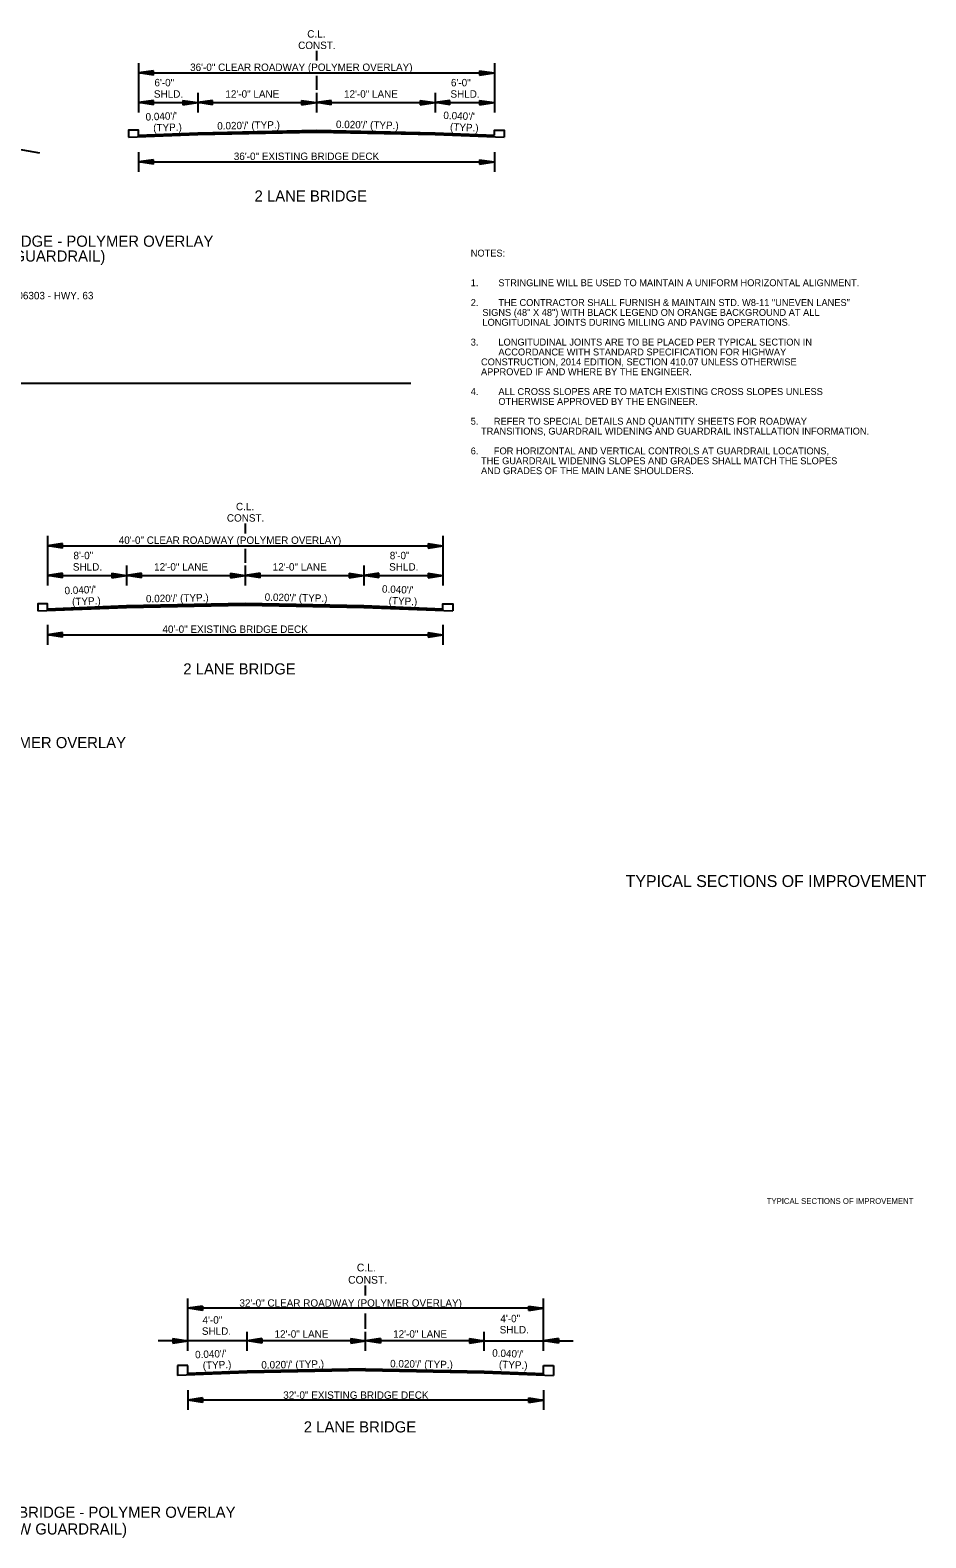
# Model space of a CAD drawing. Extents: x 545241 to 1930787, y -1971772 to 596640.
# Drawn here: x 547362 to 548268, y -1967230 to -1965705 of the extents above; entities that cross this region are included whole.
import ezdxf

# ---------------------------------------------------------------- set-up
doc = ezdxf.new("R2010")
doc.units = 0
for name, color, linetype in [('R_Border', 7, 'Continuous'), ('R_Border Notes', 7, 'Continuous'), ('R_Border Prem', 7, 'Continuous'), ('R_Draft', 7, 'Continuous')]:
    doc.layers.add(name, color=color, linetype=linetype)

# ---------------------------------------------------------------- blocks, each defined once
blk = doc.blocks.new('ARROW')
at = {"layer": 'R_Draft'}
for p, q in [((-2, 0.3), (0, 0)), ((-2, 0.3), (-2, -0.3)), ((-2, 0.25), (-0.334, 0)), ((-2, 0.199), (-0.678, 0)), ((-2, 0.149), (-1.011, 0)), ((-2, 0.097), (-1.35, 0)), ((-2, 0.047), (-1.684, 0)), ((-2, -0.3), (0, 0)), ((-2, -0.098), (-1.35, 0)), ((-2, -0.199), (-0.678, 0)), ((-2, -0.25), (-0.334, 0)), ((-2, -0.149), (-1.011, 0)), ((-2, -0.047), (-1.684, 0))]:
    blk.add_line(p, q, dxfattribs=at)

msp = doc.modelspace()

# ---------------------------------------------------------------- linework, layer by layer
at = {"layer": 'R_Border'}
for p, q in [((547651.3, -1965726.1), (547651.3, -1965736.1)), ((547471.3, -1965738.6), (547471.3, -1965788.6)), ((547471.3, -1965748.6), (547831.3, -1965748.6)), ((547831.3, -1965738.6), (547831.3, -1965788.6)), ((547651.3, -1965751.6), (547651.3, -1965765.6)), ((547471.3, -1965778.6), (547831.3, -1965778.6)), ((547531.3, -1965768.6), (547531.3, -1965788.6)), ((547651.3, -1965768.6), (547651.3, -1965788.6)), ((547771.3, -1965768.6), (547771.3, -1965788.6)), ((547271.3, -1965811.4), (547371.3, -1965829.4)), ((547471.3, -1965828.6), (547471.3, -1965848.6)), ((547471.3, -1965838.6), (547831.3, -1965838.6)), ((547831.3, -1965828.6), (547831.3, -1965848.6)), ((546718.9, -1966062.1), (547746.9, -1966062.1)), ((547579.3, -1966204.2), (547579.3, -1966214.2)), ((547379.3, -1966216.7), (547379.3, -1966266.7)), ((547779.3, -1966216.7), (547779.3, -1966266.7)), ((547379.3, -1966226.7), (547779.3, -1966226.7)), ((547579.3, -1966229.7), (547579.3, -1966243.7)), ((547459.3, -1966246.7), (547459.3, -1966266.7)), ((547579.3, -1966246.7), (547579.3, -1966266.7)), ((547699.3, -1966246.7), (547699.3, -1966266.7)), ((547379.3, -1966256.7), (547779.3, -1966256.7)), ((547379.3, -1966306.7), (547379.3, -1966326.7)), ((547779.3, -1966306.7), (547779.3, -1966326.7)), ((547379.3, -1966316.7), (547779.3, -1966316.7)), ((547521.1, -1967030.4), (547491.1, -1967030.4)), ((547881.1, -1967030.4), (547911.1, -1967030.4)), ((547521.1, -1967055.3), (547510.9, -1967055.3)), ((547510.9, -1967055.3), (547510.9, -1967065.4)), ((547521.1, -1967064.7), (547521.1, -1967055.3)), ((547881.1, -1967064.7), (547881.1, -1967055.3)), ((547881.1, -1967055.3), (547891.3, -1967055.3)), ((547891.3, -1967055.3), (547891.3, -1967065.4))]:
    msp.add_line(p, q, dxfattribs=at)
for points in [[(547471.3, -1965812.9), (547471.3, -1965806.4), (547461.3, -1965806.4), (547461.3, -1965813.6)], [(547461.3, -1965813.6), (547531.3, -1965810.8), (547651.3, -1965808.4), (547771.3, -1965810.8), (547841.3, -1965813.6)], [(547471.3, -1965811.4), (547531.3, -1965809), (547651.3, -1965806.6), (547771.3, -1965809), (547831.3, -1965811.4)], [(547471.3, -1965811.7), (547531.3, -1965809.3), (547651.3, -1965806.9), (547771.3, -1965809.3), (547831.3, -1965811.7)], [(547471.3, -1965812), (547531.3, -1965809.6), (547651.3, -1965807.2), (547771.3, -1965809.6), (547831.3, -1965812)], [(547471.3, -1965812.3), (547531.3, -1965809.9), (547651.3, -1965807.5), (547771.3, -1965809.9), (547831.3, -1965812.3)], [(547471.3, -1965812.6), (547531.3, -1965810.2), (547651.3, -1965807.8), (547771.3, -1965810.2), (547831.3, -1965812.6)], [(547471.3, -1965812.9), (547531.3, -1965810.5), (547651.3, -1965808.1), (547771.3, -1965810.5), (547831.3, -1965812.9)], [(547831.3, -1965811.4), (547831.3, -1965806.4), (547841.3, -1965806.4), (547841.3, -1965813.6)], [(547379.3, -1966291.8), (547379.3, -1966285.3), (547369.3, -1966285.3), (547369.3, -1966292.5)], [(547369.3, -1966292.5), (547459.3, -1966288.9), (547579.3, -1966286.5), (547699.3, -1966288.9), (547789.3, -1966292.5)], [(547379.3, -1966290.3), (547459.3, -1966287.1), (547579.3, -1966284.7), (547699.3, -1966287.1), (547779.3, -1966290.3)], [(547379.3, -1966290.6), (547459.3, -1966287.4), (547579.3, -1966285), (547699.3, -1966287.4), (547779.3, -1966290.6)], [(547379.3, -1966290.9), (547459.3, -1966287.7), (547579.3, -1966285.3), (547699.3, -1966287.7), (547779.3, -1966290.9)], [(547379.3, -1966291.2), (547459.3, -1966288), (547579.3, -1966285.6), (547699.3, -1966288), (547779.3, -1966291.2)], [(547379.3, -1966291.5), (547459.3, -1966288.3), (547579.3, -1966285.9), (547699.3, -1966288.3), (547779.3, -1966291.5)], [(547379.3, -1966291.8), (547459.3, -1966288.6), (547579.3, -1966286.2), (547699.3, -1966288.6), (547779.3, -1966291.8)], [(547779.3, -1966292.5), (547779.3, -1966285.3), (547789.3, -1966285.3), (547789.3, -1966292.5)]]:
    msp.add_lwpolyline(points, dxfattribs=at)
at = {"layer": 'R_Draft'}
for p, q in [((547701.1, -1966984.5), (547701.1, -1966974.5)), ((547521.1, -1967040.4), (547521.1, -1966987.5)), ((547536.1, -1966995.3), (547521.1, -1966997.5)), ((547881.1, -1966997.5), (547521.1, -1966997.5)), ((547536.1, -1966999.8), (547521.1, -1966997.5)), ((547536.1, -1966995.7), (547523.6, -1966997.5)), ((547536.1, -1966999.4), (547523.6, -1966997.5)), ((547536.1, -1966996), (547526.2, -1966997.5)), ((547536.1, -1966999), (547526.2, -1966997.5)), ((547536.1, -1966996.4), (547528.7, -1966997.5)), ((547536.1, -1966998.7), (547528.7, -1966997.5)), ((547536.1, -1966996.8), (547531.2, -1966997.5)), ((547536.1, -1966998.3), (547531.2, -1966997.5)), ((547536.1, -1966997.2), (547533.7, -1966997.5)), ((547536.1, -1966997.9), (547533.7, -1966997.5)), ((547536.1, -1966995.3), (547536.1, -1966999.8)), ((547871.1, -1966997.5), (547591.1, -1966997.5)), ((547866.1, -1966995.3), (547881.1, -1966997.5)), ((547866.1, -1966999.8), (547866.1, -1966995.3)), ((547866.1, -1966995.7), (547878.6, -1966997.5)), ((547866.1, -1966996), (547876, -1966997.5)), ((547866.1, -1966996.4), (547873.5, -1966997.5)), ((547866.1, -1966996.8), (547871, -1966997.5)), ((547866.1, -1966997.2), (547868.5, -1966997.5)), ((547866.1, -1966999.8), (547881.1, -1966997.5)), ((547866.1, -1966998.3), (547871, -1966997.5)), ((547866.1, -1966999), (547876, -1966997.5)), ((547866.1, -1966999.4), (547878.6, -1966997.5)), ((547866.1, -1966998.7), (547873.5, -1966997.5)), ((547866.1, -1966997.9), (547868.5, -1966997.5)), ((547881.1, -1967040.4), (547881.1, -1966987.6)), ((547701.1, -1967018.3), (547701.1, -1967002.6)), ((547506.1, -1967028.1), (547521.1, -1967030.4)), ((547506.1, -1967028.1), (547506.1, -1967032.6)), ((547506.1, -1967028.5), (547518.6, -1967030.4)), ((547506.1, -1967028.9), (547516, -1967030.4)), ((547506.1, -1967029.2), (547513.5, -1967030.4)), ((547506.1, -1967029.6), (547511, -1967030.4)), ((547581.1, -1967040.4), (547581.1, -1967021.2)), ((547596.1, -1967028.1), (547581.1, -1967030.4)), ((547596.1, -1967028.5), (547583.6, -1967030.4)), ((547596.1, -1967028.9), (547586.2, -1967030.4)), ((547596.1, -1967029.2), (547588.7, -1967030.4)), ((547596.1, -1967029.6), (547591.2, -1967030.4)), ((547596.1, -1967028.1), (547596.1, -1967032.6)), ((547686.1, -1967028.1), (547701.1, -1967030.4)), ((547686.1, -1967028.1), (547686.1, -1967032.6)), ((547686.1, -1967028.5), (547698.6, -1967030.4)), ((547686.1, -1967028.9), (547696, -1967030.4)), ((547686.1, -1967029.2), (547693.5, -1967030.4)), ((547686.1, -1967029.6), (547691, -1967030.4)), ((547701.1, -1967040.4), (547701.1, -1967021.2)), ((547716.1, -1967028.1), (547701.1, -1967030.4)), ((547716.1, -1967028.5), (547703.6, -1967030.4)), ((547716.1, -1967028.9), (547706.2, -1967030.4)), ((547716.1, -1967029.2), (547708.7, -1967030.4)), ((547716.1, -1967029.6), (547711.2, -1967030.4)), ((547716.1, -1967028.1), (547716.1, -1967032.6)), ((547806.1, -1967028.1), (547821.1, -1967030.4)), ((547806.1, -1967028.1), (547806.1, -1967032.6)), ((547806.1, -1967028.5), (547818.6, -1967030.4)), ((547806.1, -1967028.9), (547816, -1967030.4)), ((547806.1, -1967029.2), (547813.5, -1967030.4)), ((547806.1, -1967029.6), (547811, -1967030.4)), ((547821.1, -1967040.4), (547821.1, -1967021.2)), ((547896.1, -1967028.1), (547881.1, -1967030.4)), ((547896.1, -1967028.5), (547883.6, -1967030.4)), ((547896.1, -1967028.9), (547886.2, -1967030.4)), ((547896.1, -1967029.2), (547888.7, -1967030.4)), ((547896.1, -1967029.6), (547891.2, -1967030.4)), ((547896.1, -1967028.1), (547896.1, -1967032.6)), ((547506.1, -1967030), (547508.5, -1967030.4)), ((547506.1, -1967032.6), (547521.1, -1967030.4)), ((547506.1, -1967031.1), (547511, -1967030.4)), ((547506.1, -1967031.9), (547516, -1967030.4)), ((547506.1, -1967032.2), (547518.6, -1967030.4)), ((547506.1, -1967031.5), (547513.5, -1967030.4)), ((547506.1, -1967030.7), (547508.5, -1967030.4)), ((547581.1, -1967030.4), (547521.1, -1967030.4)), ((547701.1, -1967030.4), (547581.1, -1967030.4)), ((547596.1, -1967032.6), (547581.1, -1967030.4)), ((547596.1, -1967032.2), (547583.6, -1967030.4)), ((547596.1, -1967031.9), (547586.2, -1967030.4)), ((547596.1, -1967031.5), (547588.7, -1967030.4)), ((547596.1, -1967031.1), (547591.2, -1967030.4)), ((547596.1, -1967030), (547593.7, -1967030.4)), ((547596.1, -1967030.7), (547593.7, -1967030.4)), ((547686.1, -1967030), (547688.5, -1967030.4)), ((547686.1, -1967032.6), (547701.1, -1967030.4)), ((547686.1, -1967031.1), (547691, -1967030.4)), ((547686.1, -1967031.9), (547696, -1967030.4)), ((547686.1, -1967032.2), (547698.6, -1967030.4)), ((547686.1, -1967031.5), (547693.5, -1967030.4)), ((547686.1, -1967030.7), (547688.5, -1967030.4)), ((547821.1, -1967030.4), (547701.1, -1967030.4)), ((547716.1, -1967032.6), (547701.1, -1967030.4)), ((547716.1, -1967032.2), (547703.6, -1967030.4)), ((547716.1, -1967031.9), (547706.2, -1967030.4)), ((547716.1, -1967031.5), (547708.7, -1967030.4)), ((547716.1, -1967031.1), (547711.2, -1967030.4)), ((547716.1, -1967030), (547713.7, -1967030.4)), ((547716.1, -1967030.7), (547713.7, -1967030.4)), ((547806.1, -1967030), (547808.5, -1967030.4)), ((547806.1, -1967032.6), (547821.1, -1967030.4)), ((547806.1, -1967031.1), (547811, -1967030.4)), ((547806.1, -1967031.9), (547816, -1967030.4)), ((547806.1, -1967032.2), (547818.6, -1967030.4)), ((547806.1, -1967031.5), (547813.5, -1967030.4)), ((547806.1, -1967030.7), (547808.5, -1967030.4)), ((547821.1, -1967030.4), (547881.1, -1967030.4)), ((547896.1, -1967032.6), (547881.1, -1967030.4)), ((547896.1, -1967032.2), (547883.6, -1967030.4)), ((547896.1, -1967031.9), (547886.2, -1967030.4)), ((547896.1, -1967031.5), (547888.7, -1967030.4)), ((547896.1, -1967031.1), (547891.2, -1967030.4)), ((547896.1, -1967030), (547893.7, -1967030.4)), ((547896.1, -1967030.7), (547893.7, -1967030.4)), ((547701.1, -1967058.7), (547581.1, -1967061.1)), ((547701.1, -1967059), (547581.1, -1967061.4)), ((547701.1, -1967059.3), (547581.1, -1967061.7)), ((547701.1, -1967059.6), (547581.1, -1967062)), ((547701.1, -1967059.9), (547581.1, -1967062.3)), ((547701.1, -1967058.7), (547821.1, -1967061.1)), ((547701.1, -1967059), (547821.1, -1967061.4)), ((547701.1, -1967059.3), (547821.1, -1967061.7)), ((547701.1, -1967059.6), (547821.1, -1967062)), ((547701.1, -1967059.9), (547821.1, -1967062.3)), ((547581.1, -1967062.6), (547510.9, -1967065.4)), ((547581.1, -1967061.1), (547521.1, -1967063.5)), ((547581.1, -1967061.4), (547521.1, -1967063.8)), ((547581.1, -1967061.7), (547521.1, -1967064.1)), ((547581.1, -1967062), (547521.1, -1967064.4)), ((547581.1, -1967062.3), (547521.1, -1967064.7)), ((547701.1, -1967060.2), (547581.1, -1967062.6)), ((547701.1, -1967060.3), (547581.1, -1967062.7)), ((547701.1, -1967060.2), (547821.1, -1967062.6)), ((547701.1, -1967060.3), (547821.1, -1967062.7)), ((547821.1, -1967061.1), (547881.1, -1967063.5)), ((547821.1, -1967061.4), (547881.1, -1967063.8)), ((547821.1, -1967061.7), (547881.1, -1967064.1)), ((547821.1, -1967062), (547881.1, -1967064.4)), ((547821.1, -1967062.3), (547881.1, -1967064.7)), ((547821.1, -1967062.6), (547891.3, -1967065.4)), ((547521.1, -1967080.3), (547521.1, -1967100.3)), ((547536.1, -1967088.1), (547521.1, -1967090.3)), ((547536.1, -1967092.6), (547521.1, -1967090.3)), ((547881.1, -1967090.3), (547521.1, -1967090.3)), ((547536.1, -1967088.5), (547523.6, -1967090.3)), ((547536.1, -1967092.2), (547523.6, -1967090.3)), ((547536.1, -1967088.8), (547526.2, -1967090.3)), ((547536.1, -1967091.8), (547526.2, -1967090.3)), ((547536.1, -1967089.2), (547528.7, -1967090.3)), ((547536.1, -1967091.5), (547528.7, -1967090.3)), ((547536.1, -1967089.6), (547531.2, -1967090.3)), ((547536.1, -1967091.1), (547531.2, -1967090.3)), ((547536.1, -1967090), (547533.7, -1967090.3)), ((547536.1, -1967090.7), (547533.7, -1967090.3)), ((547536.1, -1967088.1), (547536.1, -1967092.6)), ((547866.1, -1967088.1), (547881.1, -1967090.3)), ((547866.1, -1967092.6), (547866.1, -1967088.1)), ((547866.1, -1967088.5), (547878.6, -1967090.3)), ((547866.1, -1967088.8), (547876, -1967090.3)), ((547866.1, -1967089.2), (547873.5, -1967090.3)), ((547866.1, -1967089.6), (547871, -1967090.3)), ((547866.1, -1967090), (547868.5, -1967090.3)), ((547866.1, -1967092.6), (547881.1, -1967090.3)), ((547866.1, -1967091.1), (547871, -1967090.3)), ((547866.1, -1967091.8), (547876, -1967090.3)), ((547866.1, -1967092.2), (547878.6, -1967090.3)), ((547866.1, -1967091.5), (547873.5, -1967090.3)), ((547866.1, -1967090.7), (547868.5, -1967090.3)), ((547881.1, -1967080.1), (547881.1, -1967100.1))]:
    msp.add_line(p, q, dxfattribs=at)

# ---------------------------------------------------------------- block references
at = {"layer": 'R_Border', "xscale": 7.5, "yscale": 7.5, "rotation": 180}
for p in [(547471.3, -1965748.6), (547471.3, -1965778.6), (547531.3, -1965778.6), (547651.3, -1965778.6), (547771.3, -1965778.6), (547471.3, -1965838.6), (547379.3, -1966226.7), (547379.3, -1966256.7), (547459.3, -1966256.7), (547579.3, -1966256.7), (547699.3, -1966256.7), (547379.3, -1966316.7)]:
    msp.add_blockref('ARROW', p, dxfattribs=at)
at = {"layer": 'R_Border', "xscale": 7.5, "yscale": 7.5}
for p in [(547831.3, -1965748.6), (547531.3, -1965778.6), (547651.3, -1965778.6), (547771.3, -1965778.6), (547831.3, -1965778.6), (547831.3, -1965838.6), (547779.3, -1966226.7), (547459.3, -1966256.7), (547579.3, -1966256.7), (547699.3, -1966256.7), (547779.3, -1966256.7), (547779.3, -1966316.7)]:
    msp.add_blockref('ARROW', p, dxfattribs=at)

# ---------------------------------------------------------------- texts
at = {"layer": 'R_Border'}
for s, height, p in [('CONST.', 7.5, (547632.8, -1965724.4)), ('C.L.', 7.5, (547642, -1965712.9)), ('36\'-0" CLEAR ROADWAY (POLYMER OVERLAY)', 7.5, (547523.5, -1965746.6)), ('6\'-0"', 7.5, (547487.4, -1965762.1)), ('6\'-0"', 7.5, (547787.4, -1965762.1)), ('SHLD.', 7.5, (547486.9, -1965773.6)), ('12\'-0" LANE', 7.5, (547559.2, -1965773.6)), ('12\'-0" LANE', 7.5, (547679.2, -1965773.6)), ('SHLD.', 7.5, (547786.9, -1965773.6)), ('36\'-0" EXISTING BRIDGE DECK', 7.5, (547567.7, -1965836.6)), ('2 LANE BRIDGE', 11.25, (547588.7, -1965878.6)), ('36 FT. CLEAR ROADWAY BRIDGE - POLYMER OVERLAY', 11.25, (547143.3, -1965924.3)), ('(NEW GUARDRAIL)', 11.25, (547300.7, -1965939.3)), ('- BR NO. 06303 - HWY. 63', 7.5, (547305.3, -1965977.4)), ('C.L.', 7.5, (547569.9, -1966190.7)), ('CONST.', 7.5, (547560.7, -1966202.2)), ('40\'-0" CLEAR ROADWAY (POLYMER OVERLAY)', 7.5, (547451.3, -1966224.7)), ('8\'-0"', 7.5, (547405.5, -1966240.2)), ('8\'-0"', 7.5, (547725.5, -1966240.2)), ('SHLD.', 7.5, (547404.9, -1966251.7)), ('12\'-0" LANE', 7.5, (547487.1, -1966251.7)), ('12\'-0" LANE', 7.5, (547607.1, -1966251.7)), ('SHLD.', 7.5, (547724.9, -1966251.7)), ('40\'-0" EXISTING BRIDGE DECK', 7.5, (547495.5, -1966314.7)), ('2 LANE BRIDGE', 11.25, (547516.6, -1966356.7)), ('40 FT. CLEAR ROADWAY BRIDGE - POLYMER OVERLAY', 11.25, (547054.9, -1966431.2))]:
    msp.add_text(s, height=height, dxfattribs=at).set_placement(p)
for s, height, rotation, p in [("0.040'/'", 7.5, 2.2916, (547478.6, -1965796.8)), ("0.040'/'", 7.5, 357.7084, (547779.6, -1965795.1)), ('(TYP.)', 7.5, 2.2916, (547486.3, -1965808)), ("0.020'/' (TYP.)", 7.5, 1.1458, (547551, -1965805.9)), ("0.020'/' (TYP.)", 7.5, 358.8542, (547671, -1965804.2)), ('(TYP.)', 7.5, 357.7084, (547786.3, -1965806.8)), ("0.040'/' ", 7.5, 2.2916, (547396.6, -1966275.7)), ("0.040'/'", 7.5, 357.7084, (547717.5, -1966273.9)), ('(TYP.)', 7.5, 2.2916, (547404.2, -1966286.9)), ("0.020'/' (TYP.)", 7.5, 1.1458, (547478.9, -1966283.9)), ("0.020'/' (TYP.)", 7.5, 358.8542, (547598.9, -1966282.2)), ('(TYP.)', 7.5, 357.7084, (547724.2, -1966285.7)), ('TYPICAL SECTIONS OF IMPROVEMENT', 12, 360, (547964.2, -1966571.6))]:
    msp.add_text(s, height=height, rotation=rotation, dxfattribs=at).set_placement(p)
at = {"layer": 'R_Border Notes'}
for s, p in [('NOTES: ', (547807.4, -1965934.2)), ('1.', (547807.4, -1965964.2)), ('STRINGLINE WILL BE USED TO MAINTAIN A UNIFORM HORIZONTAL ALIGNMENT.', (547835.4, -1965964.2)), ('2.', (547807.4, -1965984.2)), ('THE CONTRACTOR SHALL FURNISH & MAINTAIN STD. W8-11 "UNEVEN LANES" ', (547835.4, -1965984.2)), ('    SIGNS (48" X 48") WITH BLACK LEGEND ON ORANGE BACKGROUND AT ALL ', (547808.8, -1965994.2)), ('    LONGITUDINAL JOINTS DURING MILLING AND PAVING OPERATIONS.', (547808.8, -1966004.2)), ('3.', (547807.4, -1966024.2)), ('LONGITUDINAL JOINTS ARE TO BE PLACED PER TYPICAL SECTION IN ', (547835.4, -1966024.2)), ('    CONSTRUCTION, 2014 EDITION, SECTION 410.07 UNLESS OTHERWISE', (547807.4, -1966044.2)), ('ACCORDANCE WITH STANDARD SPECIFICATION FOR HIGHWAY', (547835.4, -1966034.2)), ('    APPROVED IF AND WHERE BY THE ENGINEER.', (547807.4, -1966054.2)), ('4.', (547807.4, -1966074.2)), ('ALL CROSS SLOPES ARE TO MATCH EXISTING CROSS SLOPES UNLESS ', (547835.4, -1966074.2)), ('OTHERWISE APPROVED BY THE ENGINEER.', (547835.4, -1966084.2)), ('5.      REFER TO SPECIAL DETAILS AND QUANTITY SHEETS FOR ROADWAY', (547807.4, -1966104.2)), ('    TRANSITIONS, GUARDRAIL WIDENING AND GUARDRAIL INSTALLATION INFORMATION.', (547807.4, -1966114.2)), ('6.      FOR HORIZONTAL AND VERTICAL CONTROLS AT GUARDRAIL LOCATIONS,', (547807.4, -1966134.2)), ('    THE GUARDRAIL WIDENING SLOPES AND GRADES SHALL MATCH THE SLOPES', (547807.4, -1966144.2)), ('    AND GRADES OF THE MAIN LANE SHOULDERS.  ', (547807.4, -1966154.2))]:
    msp.add_text(s, height=7, dxfattribs=at).set_placement(p)
at = {"layer": 'R_Border Prem'}
msp.add_text('TYPICAL SECTIONS OF IMPROVEMENT', height=5.862, rotation=360, dxfattribs=at).set_placement((548106.8, -1966892))
at = {"layer": 'R_Draft'}
for s, height, p in [('C.L.', 7.8, (547692.2, -1966960.2)), ('CONST.', 7.8, (547683.4, -1966972.6)), ('32\'-0" CLEAR ROADWAY (POLYMER OVERLAY)', 7.5, (547573.4, -1966995.9)), ('4\'-0"', 7.5, (547536.1, -1967013)), ('4\'-0"', 7.5, (547837.4, -1967011.6)), ('SHLD.', 7.5, (547535.4, -1967024.3)), ('12\'-0" LANE', 7.5, (547608.9, -1967027.2)), ('12\'-0" LANE', 7.5, (547728.9, -1967027.2)), ('SHLD.', 7.5, (547836.7, -1967022.9)), ('32\'-0" EXISTING BRIDGE DECK', 7.5, (547617.7, -1967089)), ('2 LANE BRIDGE', 11.25, (547638.5, -1967123)), ('32 FT. CLEAR ROADWAY BRIDGE - POLYMER OVERLAY', 11.25, (547165.7, -1967209.3)), ('(NEW GUARDRAIL)', 11.25, (547322.6, -1967226.2))]:
    msp.add_text(s, height=height, dxfattribs=at).set_placement(p)
for s, rotation, p in [("0.040'/'", 2.2906, (547528.7, -1967048.1)), ("0.040'/'", 357.7094, (547829, -1967046.3)), ('(TYP.)', 2.2906, (547536.4, -1967059)), ("0.020'/' (TYP.)", 0.9719, (547595.6, -1967058.5)), ("0.020'/' (TYP.)", 359.0281, (547725.8, -1967057.1)), ('(TYP.)', 357.7094, (547835.8, -1967057.8))]:
    msp.add_text(s, height=7.5, rotation=rotation, dxfattribs=at).set_placement(p)

doc.saveas('drawing.dxf')
